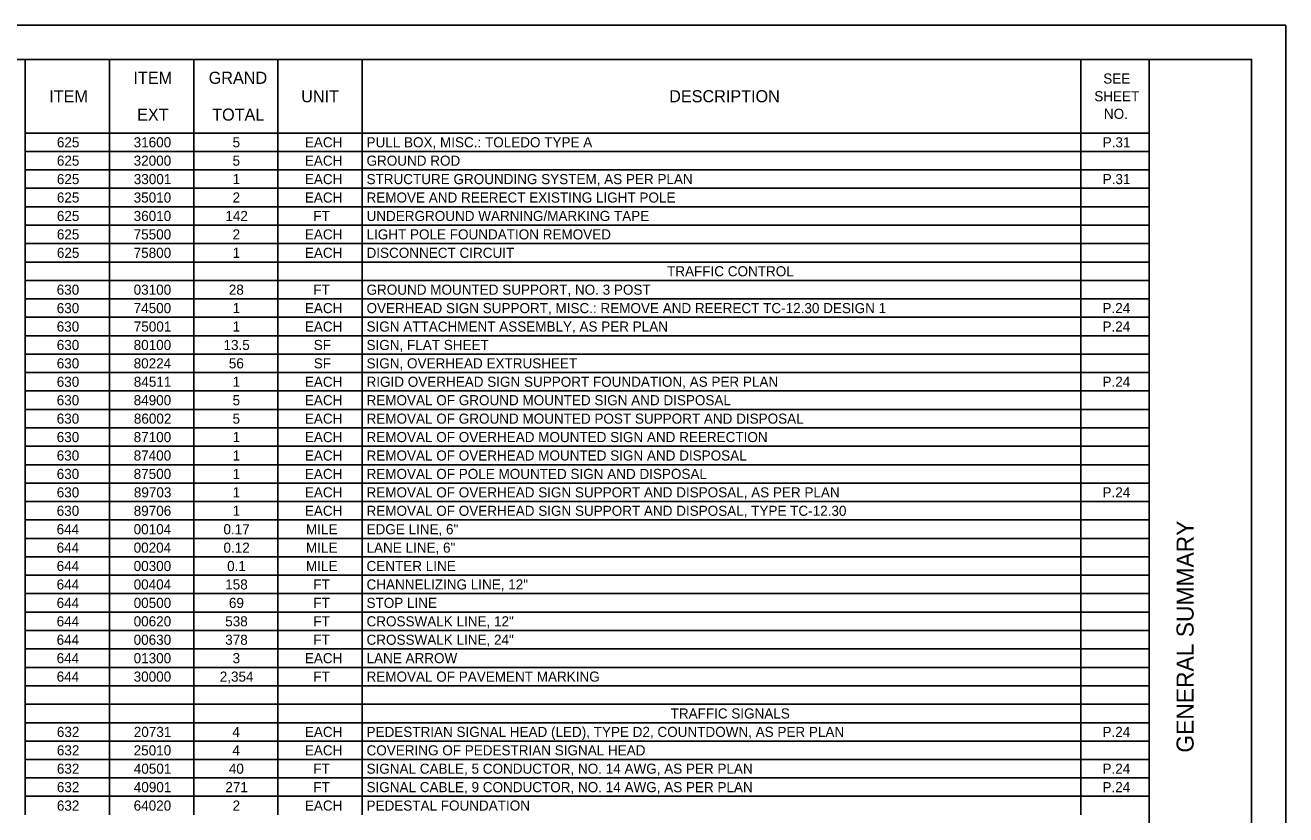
# Model space of a CAD drawing. Extents: x 0 to 34, y 0 to 22.
# Drawn here: x 15.54 to 34, y 10.43 to 22 of the extents above; entities that cross this region are included whole.
import ezdxf

# ---------------------------------------------------------------- set-up
doc = ezdxf.new("R2010")
doc.units = 0
for name, color, linetype in [('SH_Border', 7, 'Continuous'), ('SH_Cut_Line', 7, 'Continuous'), ('SH_Data', 7, 'Continuous'), ('SH_Text', 7, 'Continuous')]:
    doc.layers.add(name, color=color, linetype=linetype)

msp = doc.modelspace()

# ---------------------------------------------------------------- linework, layer by layer
at = {"layer": 'SH_Border'}
msp.add_line((32, 0.5), (32, 21.5), dxfattribs=at)
msp.add_lwpolyline([(1.5, 21.5), (33.5, 21.5), (33.5, 0.5), (1.5, 0.5)], close=True, dxfattribs=at)
at = {"layer": 'SH_Cut_Line'}
msp.add_lwpolyline([(0, 0), (34, 0), (34, 22), (0, 22)], close=True, dxfattribs=at)
at = {"layer": 'SH_Text'}
for p, q in [((15.535, 21.5), (18.003, 21.5)), ((15.535, 21.5), (15.535, 21.23)), ((16.769, 21.5), (16.769, 21.23)), ((18.003, 21.5), (19.237, 21.5)), ((18.003, 21.5), (18.003, 21.23)), ((19.237, 21.5), (32, 21.5)), ((19.237, 21.5), (19.237, 21.23)), ((20.471, 21.5), (20.471, 21.23)), ((30.997, 21.5), (30.997, 21.23)), ((32, 21.5), (32, 21.23)), ((15.535, 21.23), (15.535, 20.96)), ((16.769, 21.23), (16.769, 20.96)), ((18.003, 21.23), (18.003, 20.96)), ((19.237, 21.23), (19.237, 20.96)), ((20.471, 21.23), (20.471, 20.96)), ((30.997, 21.23), (30.997, 20.96)), ((32, 21.23), (32, 20.96)), ((15.535, 20.96), (15.535, 20.69)), ((16.769, 20.96), (16.769, 20.69)), ((18.003, 20.96), (18.003, 20.69)), ((19.237, 20.96), (19.237, 20.69)), ((20.471, 20.96), (20.471, 20.69)), ((30.997, 20.96), (30.997, 20.69)), ((32, 20.96), (32, 20.69)), ((15.535, 20.69), (15.535, 20.42)), ((16.769, 20.69), (16.769, 20.42)), ((18.003, 20.69), (18.003, 20.42)), ((19.237, 20.69), (19.237, 20.42)), ((20.471, 20.69), (20.471, 20.42)), ((30.997, 20.69), (30.997, 20.42)), ((32, 20.69), (32, 20.42)), ((15.535, 20.42), (18.003, 20.42)), ((15.535, 20.42), (15.535, 20.15)), ((16.769, 20.42), (16.769, 20.15)), ((18.003, 20.42), (19.237, 20.42)), ((18.003, 20.42), (18.003, 20.15)), ((19.237, 20.42), (32, 20.42)), ((19.237, 20.42), (19.237, 20.15)), ((20.471, 20.42), (20.471, 20.15)), ((30.997, 20.42), (30.997, 20.15)), ((32, 20.42), (32, 20.15)), ((15.535, 20.15), (18.003, 20.15)), ((15.535, 20.15), (15.535, 18.801)), ((16.769, 20.15), (16.769, 18.801)), ((18.003, 20.15), (19.237, 20.15)), ((18.003, 20.15), (18.003, 18.801)), ((19.237, 20.15), (32, 20.15)), ((19.237, 20.15), (19.237, 18.801)), ((20.471, 20.15), (20.471, 18.801)), ((30.997, 20.15), (30.997, 18.801)), ((32, 20.15), (32, 18.801)), ((15.535, 19.881), (18.003, 19.881)), ((18.003, 19.881), (19.237, 19.881)), ((19.237, 19.881), (32, 19.881)), ((15.535, 19.611), (18.003, 19.611)), ((18.003, 19.611), (19.237, 19.611)), ((19.237, 19.611), (32, 19.611)), ((15.535, 19.341), (18.003, 19.341)), ((18.003, 19.341), (19.237, 19.341)), ((19.237, 19.341), (32, 19.341)), ((15.535, 19.071), (18.003, 19.071)), ((18.003, 19.071), (19.237, 19.071)), ((19.237, 19.071), (32, 19.071)), ((15.535, 18.801), (18.003, 18.801)), ((15.535, 18.801), (15.535, 18.261)), ((16.769, 18.801), (16.769, 18.261)), ((18.003, 18.801), (19.237, 18.801)), ((18.003, 18.801), (18.003, 18.261)), ((19.237, 18.801), (32, 18.801)), ((19.237, 18.801), (19.237, 18.261)), ((20.471, 18.801), (20.471, 18.261)), ((30.997, 18.801), (30.997, 18.261)), ((32, 18.801), (32, 18.261)), ((15.535, 18.531), (18.003, 18.531)), ((18.003, 18.531), (19.237, 18.531)), ((19.237, 18.531), (32, 18.531)), ((15.535, 18.261), (18.003, 18.261)), ((15.535, 18.261), (15.535, 17.991)), ((16.769, 18.261), (16.769, 17.991)), ((18.003, 18.261), (19.237, 18.261)), ((18.003, 18.261), (18.003, 17.991)), ((19.237, 18.261), (32, 18.261)), ((19.237, 18.261), (19.237, 17.991)), ((20.471, 18.261), (20.471, 17.991)), ((30.997, 18.261), (30.997, 17.991)), ((32, 18.261), (32, 17.991)), ((15.535, 17.991), (18.003, 17.991)), ((15.535, 17.991), (15.535, 17.721)), ((16.769, 17.991), (16.769, 17.721)), ((18.003, 17.991), (19.237, 17.991)), ((18.003, 17.991), (18.003, 17.721)), ((19.237, 17.991), (32, 17.991)), ((19.237, 17.991), (19.237, 17.721)), ((20.471, 17.991), (20.471, 17.721)), ((30.997, 17.991), (30.997, 17.721)), ((32, 17.991), (32, 17.721)), ((15.535, 17.721), (18.003, 17.721)), ((15.535, 17.721), (15.535, 17.451)), ((16.769, 17.721), (16.769, 17.451)), ((18.003, 17.721), (19.237, 17.721)), ((18.003, 17.721), (18.003, 17.451)), ((19.237, 17.721), (32, 17.721)), ((19.237, 17.721), (19.237, 17.451)), ((20.471, 17.721), (20.471, 17.451)), ((30.997, 17.721), (30.997, 17.451)), ((32, 17.721), (32, 17.451)), ((15.535, 17.451), (18.003, 17.451)), ((15.535, 17.451), (15.535, 17.181)), ((16.769, 17.451), (16.769, 17.181)), ((18.003, 17.451), (19.237, 17.451)), ((18.003, 17.451), (18.003, 17.181)), ((19.237, 17.451), (32, 17.451)), ((19.237, 17.451), (19.237, 17.181)), ((20.471, 17.451), (20.471, 17.181)), ((30.997, 17.451), (30.997, 17.181)), ((32, 17.451), (32, 17.181)), ((15.535, 17.181), (18.003, 17.181)), ((15.535, 17.181), (15.535, 16.912)), ((16.769, 17.181), (16.769, 16.912)), ((18.003, 17.181), (19.237, 17.181)), ((18.003, 17.181), (18.003, 16.912)), ((19.237, 17.181), (32, 17.181)), ((19.237, 17.181), (19.237, 16.912)), ((20.471, 17.181), (20.471, 16.912)), ((30.997, 17.181), (30.997, 16.912)), ((32, 17.181), (32, 16.912)), ((15.535, 16.912), (18.003, 16.912)), ((15.535, 16.912), (15.535, 16.372)), ((16.769, 16.912), (16.769, 16.372)), ((18.003, 16.912), (19.237, 16.912)), ((18.003, 16.912), (18.003, 16.372)), ((19.237, 16.912), (32, 16.912)), ((19.237, 16.912), (19.237, 16.372)), ((20.471, 16.912), (20.471, 16.372)), ((30.997, 16.912), (30.997, 16.372)), ((32, 16.912), (32, 16.372)), ((15.535, 16.642), (18.003, 16.642)), ((18.003, 16.642), (19.237, 16.642)), ((19.237, 16.642), (32, 16.642)), ((15.535, 16.372), (18.003, 16.372)), ((15.535, 16.372), (15.535, 16.102)), ((16.769, 16.372), (16.769, 16.102)), ((18.003, 16.372), (19.237, 16.372)), ((18.003, 16.372), (18.003, 16.102)), ((19.237, 16.372), (32, 16.372)), ((19.237, 16.372), (19.237, 16.102)), ((20.471, 16.372), (20.471, 16.102)), ((30.997, 16.372), (30.997, 16.102)), ((32, 16.372), (32, 16.102)), ((15.535, 16.102), (18.003, 16.102)), ((15.535, 16.102), (15.535, 15.832)), ((16.769, 16.102), (16.769, 15.832)), ((18.003, 16.102), (19.237, 16.102)), ((18.003, 16.102), (18.003, 15.832)), ((19.237, 16.102), (32, 16.102)), ((19.237, 16.102), (19.237, 15.832)), ((20.471, 16.102), (20.471, 15.832)), ((30.997, 16.102), (30.997, 15.832)), ((32, 16.102), (32, 15.832)), ((15.535, 15.832), (18.003, 15.832)), ((15.535, 15.832), (15.535, 15.562)), ((16.769, 15.832), (16.769, 15.562)), ((18.003, 15.832), (19.237, 15.832)), ((18.003, 15.832), (18.003, 15.562)), ((19.237, 15.832), (32, 15.832)), ((19.237, 15.832), (19.237, 15.562)), ((20.471, 15.832), (20.471, 15.562)), ((30.997, 15.832), (30.997, 15.562)), ((32, 15.832), (32, 15.562)), ((15.535, 15.562), (18.003, 15.562)), ((15.535, 15.562), (15.535, 15.022)), ((16.769, 15.562), (16.769, 15.022)), ((18.003, 15.562), (19.237, 15.562)), ((18.003, 15.562), (18.003, 15.022)), ((19.237, 15.562), (32, 15.562)), ((19.237, 15.562), (19.237, 15.022)), ((20.471, 15.562), (20.471, 15.022)), ((30.997, 15.562), (30.997, 15.022)), ((32, 15.562), (32, 15.022)), ((15.535, 15.292), (18.003, 15.292)), ((18.003, 15.292), (19.237, 15.292)), ((19.237, 15.292), (32, 15.292)), ((15.535, 15.022), (18.003, 15.022)), ((15.535, 15.022), (15.535, 14.752)), ((16.769, 15.022), (16.769, 14.752)), ((18.003, 15.022), (19.237, 15.022)), ((18.003, 15.022), (18.003, 14.752)), ((19.237, 15.022), (32, 15.022)), ((19.237, 15.022), (19.237, 14.752)), ((20.471, 15.022), (20.471, 14.752)), ((30.997, 15.022), (30.997, 14.752)), ((32, 15.022), (32, 14.752)), ((15.535, 14.752), (18.003, 14.752)), ((15.535, 14.752), (15.535, 14.482)), ((16.769, 14.752), (16.769, 14.482)), ((18.003, 14.752), (19.237, 14.752)), ((18.003, 14.752), (18.003, 14.482)), ((19.237, 14.752), (32, 14.752)), ((19.237, 14.752), (19.237, 14.482)), ((20.471, 14.752), (20.471, 14.482)), ((30.997, 14.752), (30.997, 14.482)), ((32, 14.752), (32, 14.482)), ((15.535, 14.482), (18.003, 14.482)), ((15.535, 14.482), (15.535, 14.212)), ((16.769, 14.482), (16.769, 14.212)), ((18.003, 14.482), (19.237, 14.482)), ((18.003, 14.482), (18.003, 14.212)), ((19.237, 14.482), (32, 14.482)), ((19.237, 14.482), (19.237, 14.212)), ((20.471, 14.482), (20.471, 14.212)), ((30.997, 14.482), (30.997, 14.212)), ((32, 14.482), (32, 14.212)), ((15.535, 14.212), (18.003, 14.212)), ((15.535, 14.212), (15.535, 12.053)), ((16.769, 14.212), (16.769, 12.053)), ((18.003, 14.212), (19.237, 14.212)), ((18.003, 14.212), (18.003, 12.053)), ((19.237, 14.212), (32, 14.212)), ((19.237, 14.212), (19.237, 12.053)), ((20.471, 14.212), (20.471, 12.053)), ((30.997, 14.212), (30.997, 12.053)), ((32, 14.212), (32, 12.053)), ((15.535, 13.942), (18.003, 13.942)), ((18.003, 13.942), (19.237, 13.942)), ((19.237, 13.942), (32, 13.942)), ((15.535, 13.673), (18.003, 13.673)), ((18.003, 13.673), (19.237, 13.673)), ((19.237, 13.673), (32, 13.673)), ((15.535, 13.403), (18.003, 13.403)), ((18.003, 13.403), (19.237, 13.403)), ((19.237, 13.403), (32, 13.403)), ((15.535, 13.133), (18.003, 13.133)), ((18.003, 13.133), (19.237, 13.133)), ((19.237, 13.133), (32, 13.133)), ((15.535, 12.863), (18.003, 12.863)), ((18.003, 12.863), (19.237, 12.863)), ((19.237, 12.863), (32, 12.863)), ((15.535, 12.593), (18.003, 12.593)), ((18.003, 12.593), (19.237, 12.593)), ((19.237, 12.593), (32, 12.593)), ((15.535, 12.323), (18.003, 12.323)), ((18.003, 12.323), (19.237, 12.323)), ((19.237, 12.323), (32, 12.323)), ((15.535, 12.053), (18.003, 12.053)), ((15.535, 12.053), (15.535, 11.783)), ((16.769, 12.053), (16.769, 11.783)), ((18.003, 12.053), (19.237, 12.053)), ((18.003, 12.053), (18.003, 11.783)), ((19.237, 12.053), (32, 12.053)), ((19.237, 12.053), (19.237, 11.783)), ((20.471, 12.053), (20.471, 11.783)), ((30.997, 12.053), (30.997, 11.783)), ((32, 12.053), (32, 11.783)), ((15.535, 11.783), (18.003, 11.783)), ((15.535, 11.783), (15.535, 10.704)), ((16.769, 11.783), (16.769, 10.704)), ((18.003, 11.783), (19.237, 11.783)), ((18.003, 11.783), (18.003, 10.704)), ((19.237, 11.783), (32, 11.783)), ((19.237, 11.783), (19.237, 10.704)), ((20.471, 11.783), (20.471, 10.704)), ((30.997, 11.783), (30.997, 10.704)), ((32, 11.783), (32, 10.704)), ((15.535, 11.513), (18.003, 11.513)), ((18.003, 11.513), (19.237, 11.513)), ((19.237, 11.513), (32, 11.513)), ((15.535, 11.243), (18.003, 11.243)), ((18.003, 11.243), (19.237, 11.243)), ((19.237, 11.243), (32, 11.243)), ((15.535, 10.973), (18.003, 10.973)), ((18.003, 10.973), (19.237, 10.973)), ((19.237, 10.973), (32, 10.973)), ((15.535, 10.704), (18.003, 10.704)), ((15.535, 10.704), (15.535, 10.434)), ((16.769, 10.704), (16.769, 10.434)), ((18.003, 10.704), (19.237, 10.704)), ((18.003, 10.704), (18.003, 10.434)), ((19.237, 10.704), (32, 10.704)), ((19.237, 10.704), (19.237, 10.434)), ((20.471, 10.704), (20.471, 10.434)), ((30.997, 10.704), (30.997, 10.434)), ((32, 10.704), (32, 10.434))]:
    msp.add_line(p, q, dxfattribs=at)

# ---------------------------------------------------------------- texts
at = {"layer": 'SH_Data'}
msp.add_text('GENERAL SUMMARY', height=0.25, rotation=90, dxfattribs=at).set_placement((32.65, 11.344))
at = {"layer": 'SH_Text'}
for s, height, p in [('ITEM', 0.1774, (17.121, 21.141)), ('GRAND', 0.1774, (18.223, 21.141)), ('SEE ', 0.1478, (31.326, 21.145)), ('DESCRIPTION', 0.17737, (24.968, 20.871)), ('ITEM', 0.1774, (15.887, 20.871)), ('UNIT', 0.1774, (19.578, 20.871)), ('SHEET ', 0.1478, (31.195, 20.886)), ('EXT', 0.1774, (17.174, 20.602)), ('TOTAL', 0.1774, (18.274, 20.602)), ('NO.', 0.1478, (31.336, 20.628)), ('625', 0.1478, (15.999, 20.211)), ('31600', 0.1478, (17.124, 20.211)), ('5', 0.148, (18.573, 20.211)), ('EACH', 0.1478, (19.632, 20.211)), ('PULL BOX, MISC.: TOLEDO TYPE A', 0.14781, (20.535, 20.211)), ('P.31', 0.1478, (31.318, 20.211)), ('625', 0.1478, (15.999, 19.942)), ('32000', 0.1478, (17.124, 19.942)), ('5', 0.148, (18.573, 19.942)), ('EACH', 0.1478, (19.632, 19.942)), ('GROUND ROD', 0.1478, (20.535, 19.942)), ('625', 0.1478, (15.999, 19.672)), ('33001', 0.1478, (17.126, 19.672)), ('1', 0.148, (18.573, 19.672)), ('EACH', 0.1478, (19.632, 19.672)), ('STRUCTURE GROUNDING SYSTEM, AS PER PLAN', 0.14781, (20.535, 19.672)), ('P.31', 0.1478, (31.318, 19.672)), ('625', 0.1478, (15.999, 19.402)), ('35010', 0.1478, (17.124, 19.402)), ('2', 0.148, (18.573, 19.402)), ('EACH', 0.1478, (19.632, 19.402)), ('REMOVE AND REERECT EXISTING LIGHT POLE', 0.14781, (20.535, 19.402)), ('625', 0.1478, (15.999, 19.132)), ('36010', 0.1478, (17.124, 19.132)), ('142', 0.1478, (18.467, 19.132)), ('FT', 0.1478, (19.756, 19.132)), ('UNDERGROUND WARNING/MARKING TAPE', 0.14781, (20.535, 19.132)), ('625', 0.1478, (15.999, 18.862)), ('75500', 0.1478, (17.124, 18.862)), ('2', 0.148, (18.573, 18.862)), ('EACH', 0.1478, (19.632, 18.862)), ('LIGHT POLE FOUNDATION REMOVED', 0.14781, (20.535, 18.862)), ('625', 0.1478, (15.999, 18.592)), ('75800', 0.1478, (17.124, 18.592)), ('1', 0.148, (18.573, 18.592)), ('EACH', 0.1478, (19.632, 18.592)), ('DISCONNECT CIRCUIT', 0.14781, (20.535, 18.592)), ('TRAFFIC CONTROL', 0.14781, (24.937, 18.322)), ('630', 0.1478, (15.997, 18.052)), ('03100', 0.1478, (17.124, 18.052)), ('28', 0.1478, (18.518, 18.052)), ('FT', 0.1478, (19.756, 18.052)), ('GROUND MOUNTED SUPPORT, NO. 3 POST', 0.14781, (20.535, 18.052)), ('630', 0.1478, (15.997, 17.782)), ('74500', 0.1478, (17.124, 17.782)), ('1', 0.148, (18.573, 17.782)), ('EACH', 0.1478, (19.632, 17.782)), ('OVERHEAD SIGN SUPPORT, MISC.: REMOVE AND REERECT TC-12.30 DESIGN 1', 0.14781, (20.535, 17.782)), ('P.24', 0.1478, (31.315, 17.782)), ('630', 0.1478, (15.997, 17.512)), ('75001', 0.1478, (17.126, 17.512)), ('1', 0.148, (18.573, 17.512)), ('EACH', 0.1478, (19.632, 17.512)), ('SIGN ATTACHMENT ASSEMBLY, AS PER PLAN', 0.14781, (20.535, 17.512)), ('P.24', 0.1478, (31.315, 17.512)), ('630', 0.1478, (15.997, 17.242)), ('80100', 0.1478, (17.124, 17.242)), ('13.5', 0.1478, (18.44, 17.242)), ('SF', 0.1478, (19.762, 17.242)), ('SIGN, FLAT SHEET', 0.14781, (20.535, 17.242)), ('630', 0.1478, (15.997, 16.973)), ('80224', 0.1478, (17.124, 16.973)), ('56', 0.1478, (18.518, 16.973)), ('SF', 0.1478, (19.762, 16.973)), ('SIGN, OVERHEAD EXTRUSHEET', 0.14781, (20.535, 16.973)), ('630', 0.1478, (15.997, 16.703)), ('84511', 0.1478, (17.126, 16.703)), ('1', 0.148, (18.573, 16.703)), ('EACH', 0.1478, (19.632, 16.703)), ('RIGID OVERHEAD SIGN SUPPORT FOUNDATION, AS PER PLAN', 0.14781, (20.535, 16.703)), ('P.24', 0.1478, (31.315, 16.703)), ('630', 0.1478, (15.997, 16.433)), ('84900', 0.1478, (17.124, 16.433)), ('5', 0.148, (18.573, 16.433)), ('EACH', 0.1478, (19.632, 16.433)), ('REMOVAL OF GROUND MOUNTED SIGN AND DISPOSAL', 0.14781, (20.535, 16.433)), ('630', 0.1478, (15.997, 16.163)), ('86002', 0.1478, (17.127, 16.163)), ('5', 0.148, (18.573, 16.163)), ('EACH', 0.1478, (19.632, 16.163)), ('REMOVAL OF GROUND MOUNTED POST SUPPORT AND DISPOSAL', 0.14781, (20.535, 16.163)), ('630', 0.1478, (15.997, 15.893)), ('87100', 0.1478, (17.124, 15.893)), ('1', 0.148, (18.573, 15.893)), ('EACH', 0.1478, (19.632, 15.893)), ('REMOVAL OF OVERHEAD MOUNTED SIGN AND REERECTION', 0.14781, (20.535, 15.893)), ('630', 0.1478, (15.997, 15.623)), ('87400', 0.1478, (17.124, 15.623)), ('1', 0.148, (18.573, 15.623)), ('EACH', 0.1478, (19.632, 15.623)), ('REMOVAL OF OVERHEAD MOUNTED SIGN AND DISPOSAL', 0.14781, (20.535, 15.623)), ('630', 0.1478, (15.997, 15.353)), ('87500', 0.1478, (17.124, 15.353)), ('1', 0.148, (18.573, 15.353)), ('EACH', 0.1478, (19.632, 15.353)), ('REMOVAL OF POLE MOUNTED SIGN AND DISPOSAL', 0.14781, (20.535, 15.353)), ('630', 0.1478, (15.997, 15.083)), ('89703', 0.1478, (17.127, 15.083)), ('1', 0.148, (18.573, 15.083)), ('EACH', 0.1478, (19.632, 15.083)), ('REMOVAL OF OVERHEAD SIGN SUPPORT AND DISPOSAL, AS PER PLAN', 0.14781, (20.535, 15.083)), ('P.24', 0.1478, (31.315, 15.083)), ('630', 0.1478, (15.997, 14.813)), ('89706', 0.1478, (17.125, 14.813)), ('1', 0.148, (18.573, 14.813)), ('EACH', 0.1478, (19.632, 14.813)), ('REMOVAL OF OVERHEAD SIGN SUPPORT AND DISPOSAL, TYPE TC-12.30', 0.14781, (20.535, 14.813)), ('644', 0.1478, (15.996, 14.543)), ('00104', 0.1478, (17.124, 14.543)), ('0.17', 0.1478, (18.439, 14.543)), ('MILE', 0.1478, (19.648, 14.543)), ('EDGE LINE, 6"', 0.14781, (20.535, 14.543)), ('644', 0.1478, (15.996, 14.273)), ('00204', 0.1478, (17.124, 14.273)), ('0.12', 0.1478, (18.44, 14.273)), ('MILE', 0.1478, (19.648, 14.273)), ('LANE LINE, 6"', 0.14781, (20.535, 14.273)), ('644', 0.1478, (15.996, 14.004)), ('00300', 0.1478, (17.124, 14.004)), ('0.1', 0.1478, (18.493, 14.004)), ('MILE', 0.1478, (19.648, 14.004)), ('CENTER LINE', 0.14781, (20.535, 14.004)), ('644', 0.1478, (15.996, 13.734)), ('00404', 0.1478, (17.124, 13.734)), ('158', 0.1478, (18.465, 13.734)), ('FT', 0.1478, (19.756, 13.734)), ('CHANNELIZING LINE, 12"', 0.14781, (20.535, 13.734)), ('644', 0.1478, (15.996, 13.464)), ('00500', 0.1478, (17.124, 13.464)), ('69', 0.1478, (18.519, 13.464)), ('FT', 0.1478, (19.756, 13.464)), ('STOP LINE', 0.1478, (20.535, 13.464)), ('644', 0.1478, (15.996, 13.194)), ('00620', 0.1478, (17.124, 13.194)), ('538', 0.1478, (18.465, 13.194)), ('FT', 0.1478, (19.756, 13.194)), ('CROSSWALK LINE, 12"', 0.14781, (20.535, 13.194)), ('644', 0.1478, (15.996, 12.924)), ('00630', 0.1478, (17.124, 12.924)), ('378', 0.1478, (18.465, 12.924)), ('FT', 0.1478, (19.756, 12.924)), ('CROSSWALK LINE, 24"', 0.14781, (20.535, 12.924)), ('644', 0.1478, (15.996, 12.654)), ('01300', 0.1478, (17.124, 12.654)), ('3', 0.148, (18.573, 12.654)), ('EACH', 0.1478, (19.632, 12.654)), ('LANE ARROW', 0.1478, (20.535, 12.654)), ('644', 0.1478, (15.996, 12.384)), ('30000', 0.1478, (17.124, 12.384)), ('2,354', 0.1478, (18.385, 12.384)), ('FT', 0.1478, (19.756, 12.384)), ('REMOVAL OF PAVEMENT MARKING', 0.14781, (20.535, 12.384)), ('TRAFFIC SIGNALS', 0.14781, (24.989, 11.844)), ('632', 0.1478, (15.999, 11.574)), ('20731', 0.1478, (17.126, 11.574)), ('4', 0.148, (18.57, 11.574)), ('EACH', 0.1478, (19.632, 11.574)), ('PEDESTRIAN SIGNAL HEAD (LED), TYPE D2, COUNTDOWN, AS PER PLAN', 0.14781, (20.535, 11.574)), ('P.24', 0.1478, (31.315, 11.574)), ('632', 0.1478, (15.999, 11.304)), ('25010', 0.1478, (17.124, 11.304)), ('4', 0.148, (18.57, 11.304)), ('EACH', 0.1478, (19.632, 11.304)), ('COVERING OF PEDESTRIAN SIGNAL HEAD', 0.14781, (20.535, 11.304)), ('632', 0.1478, (15.999, 11.035)), ('40501', 0.1478, (17.126, 11.035)), ('40', 0.1478, (18.518, 11.035)), ('FT', 0.1478, (19.756, 11.035)), ('SIGNAL CABLE, 5 CONDUCTOR, NO. 14 AWG, AS PER PLAN', 0.14781, (20.535, 11.035)), ('P.24', 0.1478, (31.315, 11.035)), ('632', 0.1478, (15.999, 10.765)), ('40901', 0.1478, (17.126, 10.765)), ('271', 0.1478, (18.467, 10.765)), ('FT', 0.1478, (19.756, 10.765)), ('SIGNAL CABLE, 9 CONDUCTOR, NO. 14 AWG, AS PER PLAN', 0.14781, (20.535, 10.765)), ('P.24', 0.1478, (31.315, 10.765)), ('632', 0.1478, (15.999, 10.495)), ('64020', 0.1478, (17.124, 10.495)), ('2', 0.148, (18.573, 10.495)), ('EACH', 0.1478, (19.632, 10.495)), ('PEDESTAL FOUNDATION', 0.14781, (20.535, 10.495))]:
    msp.add_text(s, height=height, dxfattribs=at).set_placement(p)

doc.saveas('drawing.dxf')
